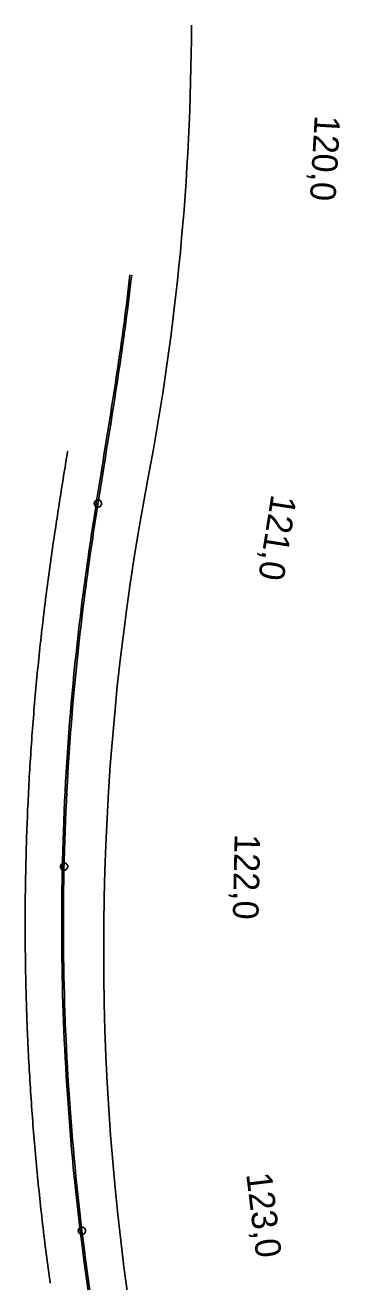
# Model space of a CAD drawing. Extents: x -670810 to -649614, y -1131928 to -1115069.
# Drawn here: x -670810 to -669949, y -1118513 to -1115069 of the extents above; entities that cross this region are included whole.
import ezdxf

# ---------------------------------------------------------------- set-up
doc = ezdxf.new("R2010")
doc.units = 0
for name, color, linetype in [('hranice_VRT_ZUR_Vysocina', 7, 'Continuous'), ('Situace - Osa koleje 2D', 7, 'Continuous'), ('Situace - Osa koleje tunel 2D', 7, 'Continuous'), ('Staničení - hlavní staničení + kolečka 1k', 7, 'Continuous')]:
    doc.layers.add(name, color=color, linetype=linetype)

# ---------------------------------------------------------------- blocks, each defined once
blk = doc.blocks.new('Sit10Kruh_98')
at = {"layer": 'Staničení - hlavní staničení + kolečka 1k'}
blk.add_lwpolyline([(10, 0), (10, 0.6), (9.9, 1.3), (9.8, 1.9), (9.7, 2.5), (9.5, 3.1), (9.3, 3.7), (9, 4.3), (8.8, 4.8), (8.4, 5.4), (8.1, 5.9), (7.7, 6.4), (7.3, 6.8), (6.8, 7.3), (6.4, 7.7), (5.9, 8.1), (5.4, 8.4), (4.8, 8.8), (4.3, 9), (3.7, 9.3), (3.1, 9.5), (2.5, 9.7), (1.9, 9.8), (1.3, 9.9), (0.6, 10), (0, 10), (-0.6, 10), (-1.3, 9.9), (-1.9, 9.8), (-2.5, 9.7), (-3.1, 9.5), (-3.7, 9.3), (-4.3, 9), (-4.8, 8.8), (-5.4, 8.4), (-5.9, 8.1), (-6.4, 7.7), (-6.8, 7.3), (-7.3, 6.8), (-7.7, 6.4), (-8.1, 5.9), (-8.4, 5.4), (-8.8, 4.8), (-9, 4.3), (-9.3, 3.7), (-9.5, 3.1), (-9.7, 2.5), (-9.8, 1.9), (-9.9, 1.3), (-10, 0.6), (-10, 0), (-10, -0.6), (-9.9, -1.3), (-9.8, -1.9), (-9.7, -2.5), (-9.5, -3.1), (-9.3, -3.7), (-9, -4.3), (-8.8, -4.8), (-8.4, -5.4), (-8.1, -5.9), (-7.7, -6.4), (-7.3, -6.8), (-6.8, -7.3), (-6.4, -7.7), (-5.9, -8.1), (-5.4, -8.4), (-4.8, -8.8), (-4.3, -9), (-3.7, -9.3), (-3.1, -9.5), (-2.5, -9.7), (-1.9, -9.8), (-1.3, -9.9), (-0.6, -10), (0, -10), (0.6, -10), (1.3, -9.9), (1.9, -9.8), (2.5, -9.7), (3.1, -9.5), (3.7, -9.3), (4.3, -9), (4.8, -8.8), (5.4, -8.4), (5.9, -8.1), (6.4, -7.7), (6.8, -7.3), (7.3, -6.8), (7.7, -6.4), (8.1, -5.9), (8.4, -5.4), (8.8, -4.8), (9, -4.3), (9.3, -3.7), (9.5, -3.1), (9.7, -2.5), (9.8, -1.9), (9.9, -1.3)], close=True, dxfattribs=at)
blk.add_circle((0, 0), 10, dxfattribs=at)
blk = doc.blocks.new('Sit10Kruh_99')
at = {"layer": 'Staničení - hlavní staničení + kolečka 1k'}
blk.add_lwpolyline([(10, 0), (9.98026, 0.6279), (9.92114, 1.25334), (9.82288, 1.87382), (9.68584, 2.4869), (9.51056, 3.09016), (9.29776, 3.68124), (9.04828, 4.2578), (8.76306, 4.81754), (8.44328, 5.35826), (8.09016, 5.87786), (7.70514, 6.37424), (7.28968, 6.84548), (6.84548, 7.28968), (6.37424, 7.70514), (5.87786, 8.09016), (5.35826, 8.44328), (4.81754, 8.76306), (4.2578, 9.04828), (3.68124, 9.29776), (3.09016, 9.51056), (2.4869, 9.68584), (1.87382, 9.82288), (1.25334, 9.92114), (0.6279, 9.98026), (0, 10), (-0.6279, 9.98026), (-1.25334, 9.92114), (-1.87382, 9.82288), (-2.4869, 9.68584), (-3.09016, 9.51056), (-3.68124, 9.29776), (-4.2578, 9.04828), (-4.81754, 8.76306), (-5.35826, 8.44328), (-5.87786, 8.09016), (-6.37424, 7.70514), (-6.84548, 7.28968), (-7.28968, 6.84548), (-7.70514, 6.37424), (-8.09016, 5.87786), (-8.44328, 5.35826), (-8.76306, 4.81754), (-9.04828, 4.2578), (-9.29776, 3.68124), (-9.51056, 3.09016), (-9.68584, 2.4869), (-9.82288, 1.87382), (-9.92114, 1.25334), (-9.98026, 0.6279), (-10, 0), (-9.98026, -0.6279), (-9.92114, -1.25334), (-9.82288, -1.87382), (-9.68584, -2.4869), (-9.51056, -3.09016), (-9.29776, -3.68124), (-9.04828, -4.2578), (-8.76306, -4.81754), (-8.44328, -5.35826), (-8.09016, -5.87786), (-7.70514, -6.37424), (-7.28968, -6.84548), (-6.84548, -7.28968), (-6.37424, -7.70514), (-5.87786, -8.09016), (-5.35826, -8.44328), (-4.81754, -8.76306), (-4.2578, -9.04828), (-3.68124, -9.29776), (-3.09016, -9.51056), (-2.4869, -9.68584), (-1.87382, -9.82288), (-1.25334, -9.92114), (-0.6279, -9.98026), (0, -10), (0.6279, -9.98026), (1.25334, -9.92114), (1.87382, -9.82288), (2.4869, -9.68584), (3.09016, -9.51056), (3.68124, -9.29776), (4.2578, -9.04828), (4.81754, -8.76306), (5.35826, -8.44328), (5.87786, -8.09016), (6.37424, -7.70514), (6.84548, -7.28968), (7.28968, -6.84548), (7.70514, -6.37424), (8.09016, -5.87786), (8.44328, -5.35826), (8.76306, -4.81754), (9.04828, -4.2578), (9.29776, -3.68124), (9.51056, -3.09016), (9.68584, -2.4869), (9.82288, -1.87382), (9.92114, -1.25334)], close=True, dxfattribs=at)
blk.add_circle((0, 0), 10, dxfattribs=at)
blk = doc.blocks.new('Sit10Kruh_100')
at = {"layer": 'Staničení - hlavní staničení + kolečka 1k'}
blk.add_lwpolyline([(10, 0), (10, 0.6), (9.9, 1.3), (9.8, 1.9), (9.7, 2.5), (9.5, 3.1), (9.3, 3.7), (9, 4.3), (8.8, 4.8), (8.4, 5.4), (8.1, 5.9), (7.7, 6.4), (7.3, 6.8), (6.8, 7.3), (6.4, 7.7), (5.9, 8.1), (5.4, 8.4), (4.8, 8.8), (4.3, 9), (3.7, 9.3), (3.1, 9.5), (2.5, 9.7), (1.9, 9.8), (1.3, 9.9), (0.6, 10), (0, 10), (-0.6, 10), (-1.3, 9.9), (-1.9, 9.8), (-2.5, 9.7), (-3.1, 9.5), (-3.7, 9.3), (-4.3, 9), (-4.8, 8.8), (-5.4, 8.4), (-5.9, 8.1), (-6.4, 7.7), (-6.8, 7.3), (-7.3, 6.8), (-7.7, 6.4), (-8.1, 5.9), (-8.4, 5.4), (-8.8, 4.8), (-9, 4.3), (-9.3, 3.7), (-9.5, 3.1), (-9.7, 2.5), (-9.8, 1.9), (-9.9, 1.3), (-10, 0.6), (-10, 0), (-10, -0.6), (-9.9, -1.3), (-9.8, -1.9), (-9.7, -2.5), (-9.5, -3.1), (-9.3, -3.7), (-9, -4.3), (-8.8, -4.8), (-8.4, -5.4), (-8.1, -5.9), (-7.7, -6.4), (-7.3, -6.8), (-6.8, -7.3), (-6.4, -7.7), (-5.9, -8.1), (-5.4, -8.4), (-4.8, -8.8), (-4.3, -9), (-3.7, -9.3), (-3.1, -9.5), (-2.5, -9.7), (-1.9, -9.8), (-1.3, -9.9), (-0.6, -10), (0, -10), (0.6, -10), (1.3, -9.9), (1.9, -9.8), (2.5, -9.7), (3.1, -9.5), (3.7, -9.3), (4.3, -9), (4.8, -8.8), (5.4, -8.4), (5.9, -8.1), (6.4, -7.7), (6.8, -7.3), (7.3, -6.8), (7.7, -6.4), (8.1, -5.9), (8.4, -5.4), (8.8, -4.8), (9, -4.3), (9.3, -3.7), (9.5, -3.1), (9.7, -2.5), (9.8, -1.9), (9.9, -1.3)], close=True, dxfattribs=at)
blk.add_circle((0, 0), 10, dxfattribs=at)

msp = doc.modelspace()

# ---------------------------------------------------------------- linework, layer by layer
at = {"layer": 'hranice_VRT_ZUR_Vysocina'}
msp.add_lwpolyline([(-670693.9, -1116236.6), (-670695.3, -1116246.1), (-670696.8, -1116255.2), (-670698.4, -1116265.1), (-670700, -1116275), (-670701.6, -1116284.9), (-670703.1, -1116294.8), (-670704.7, -1116304.7), (-670706.3, -1116314.6), (-670707.9, -1116324.5), (-670709.5, -1116334.4), (-670711, -1116344.4), (-670712.6, -1116354.3), (-670714.2, -1116364.2), (-670715.7, -1116374.2), (-670717.3, -1116384.1), (-670718.8, -1116394.1), (-670720.4, -1116404.1), (-670721.9, -1116414), (-670723.4, -1116424), (-670724.9, -1116434), (-670726.4, -1116444), (-670727.9, -1116453.9), (-670729.4, -1116463.9), (-670730.9, -1116473.9), (-670732.4, -1116483.9), (-670733.8, -1116493.9), (-670735.3, -1116503.9), (-670736.7, -1116514), (-670738.1, -1116524), (-670739.6, -1116534), (-670741, -1116544), (-670742.3, -1116554.1), (-670743.7, -1116564.1), (-670745.1, -1116574.2), (-670746.4, -1116584.2), (-670747.8, -1116594.2), (-670749.1, -1116604.3), (-670750.4, -1116614.4), (-670751.7, -1116624.4), (-670753, -1116634.5), (-670754.3, -1116644.5), (-670755.6, -1116654.6), (-670756.8, -1116664.7), (-670758, -1116674.8), (-670759.3, -1116684.8), (-670760.5, -1116694.9), (-670761.1, -1116700.5), (-670761.7, -1116705), (-670762.8, -1116715.1), (-670764, -1116725.2), (-670765.1, -1116735.2), (-670766.3, -1116745.3), (-670767.4, -1116755.4), (-670768.5, -1116765.5), (-670769.6, -1116775.6), (-670770.6, -1116785.7), (-670771.7, -1116795.8), (-670772.8, -1116805.9), (-670773.8, -1116816), (-670774.8, -1116826.1), (-670775.8, -1116836.2), (-670776.8, -1116846.3), (-670777.8, -1116856.4), (-670778.7, -1116866.5), (-670779.7, -1116876.6), (-670780.6, -1116886.7), (-670781.5, -1116896.8), (-670782.4, -1116906.9), (-670783.3, -1116917), (-670784.2, -1116927.1), (-670785, -1116937.2), (-670785.9, -1116947.4), (-670786.7, -1116957.5), (-670787.5, -1116967.6), (-670788.3, -1116977.7), (-670789.1, -1116987.8), (-670789.9, -1116998), (-670790.6, -1117008.1), (-670791.4, -1117018.2), (-670792.1, -1117028.3), (-670792.8, -1117038.4), (-670793.5, -1117048.6), (-670794.2, -1117058.7), (-670794.9, -1117068.8), (-670795.5, -1117079), (-670796.2, -1117089.1), (-670796.8, -1117099.2), (-670797.4, -1117109.3), (-670798, -1117119.5), (-670798.6, -1117129.6), (-670799.1, -1117139.7), (-670799.7, -1117149.9), (-670800.2, -1117160), (-670800.8, -1117170.1), (-670801.3, -1117180.3), (-670801.8, -1117190.4), (-670802.2, -1117200.6), (-670802.7, -1117210.7), (-670803.2, -1117220.8), (-670803.6, -1117231), (-670804, -1117241.1), (-670804.4, -1117251.3), (-670804.8, -1117261.4), (-670805.2, -1117271.5), (-670805.6, -1117281.7), (-670805.9, -1117291.8), (-670806.3, -1117302), (-670806.6, -1117312.1), (-670806.9, -1117322.3), (-670807.2, -1117332.4), (-670807.5, -1117342.6), (-670807.7, -1117352.7), (-670808, -1117362.8), (-670808.2, -1117373), (-670808.4, -1117383.1), (-670808.6, -1117393.3), (-670808.8, -1117403.4), (-670809, -1117413.6), (-670809.2, -1117423.7), (-670809.3, -1117433.9), (-670809.4, -1117444), (-670809.6, -1117454.2), (-670809.7, -1117464.3), (-670809.8, -1117474.5), (-670809.8, -1117484.6), (-670809.9, -1117494.8), (-670809.9, -1117504.9), (-670810, -1117515.1), (-670810, -1117525.2), (-670810, -1117535.4), (-670810, -1117545.5), (-670810, -1117555.7), (-670809.9, -1117565.8), (-670809.9, -1117576), (-670809.8, -1117586.1), (-670809.7, -1117596.3), (-670809.6, -1117606.4), (-670809.5, -1117616.6), (-670809.4, -1117626.7), (-670809.2, -1117636.9), (-670809.1, -1117647), (-670808.9, -1117657.2), (-670808.7, -1117667.3), (-670808.5, -1117677.5), (-670808.3, -1117687.6), (-670808.1, -1117697.8), (-670807.8, -1117707.9), (-670807.6, -1117718), (-670807.3, -1117728.2), (-670807, -1117738.3), (-670806.7, -1117748.5), (-670806.4, -1117758.6), (-670806.1, -1117768.8), (-670805.7, -1117778.9), (-670805.4, -1117789.1), (-670805, -1117799.2), (-670804.6, -1117809.3), (-670804.2, -1117819.5), (-670803.8, -1117829.6), (-670803.3, -1117839.8), (-670802.9, -1117849.9), (-670802.4, -1117860), (-670802, -1117870.2), (-670801.5, -1117880.3), (-670801, -1117890.5), (-670800.5, -1117900.6), (-670799.9, -1117910.7), (-670799.4, -1117920.9), (-670798.8, -1117931), (-670798.2, -1117941.1), (-670797.6, -1117951.3), (-670797, -1117961.4), (-670796.4, -1117971.5), (-670795.8, -1117981.7), (-670795.1, -1117991.8), (-670794.5, -1118001.9), (-670793.8, -1118012), (-670793.1, -1118022.2), (-670792.4, -1118032.3), (-670791.7, -1118042.4), (-670790.9, -1118052.5), (-670790.2, -1118062.7), (-670789.4, -1118072.8), (-670788.6, -1118082.9), (-670787.8, -1118093), (-670787, -1118103.1), (-670786.2, -1118113.3), (-670785.4, -1118123.4), (-670784.5, -1118133.5), (-670783.7, -1118143.6), (-670782.8, -1118153.7), (-670781.9, -1118163.8), (-670781, -1118173.9), (-670780.1, -1118184), (-670779.1, -1118194.1), (-670778.2, -1118204.2), (-670777.2, -1118214.3), (-670776.2, -1118224.4), (-670775.2, -1118234.5), (-670774.2, -1118244.6), (-670773.2, -1118254.7), (-670772.1, -1118264.8), (-670771.1, -1118274.9), (-670770, -1118285), (-670768.9, -1118295.1), (-670767.8, -1118305.2), (-670766.7, -1118315.3), (-670765.6, -1118325.4), (-670764.5, -1118335.5), (-670763.3, -1118345.6), (-670762.1, -1118355.6), (-670761, -1118365.7), (-670759.8, -1118375.8), (-670758.6, -1118385.9), (-670757.3, -1118395.9), (-670756.1, -1118406), (-670754.8, -1118416.1), (-670753.6, -1118426.2), (-670752.3, -1118436.2), (-670751, -1118446.3), (-670749.7, -1118456.4), (-670748.3, -1118466.4), (-670747, -1118476.5), (-670745.6, -1118486.5), (-670744.3, -1118496.6), (-670742.9, -1118506.7), (-670741.5, -1118516.7)], dxfattribs=at)
for centre, radius, start, end in [((-677058.9, -1115053.7), 6704.1, 349.21643, 359.86609), ((-663695.1, -1117599), 6900, 169.21643, 188.47877)]:
    msp.add_arc(centre, radius, start, end, dxfattribs=at)
at = {"layer": 'Situace - Osa koleje 2D'}
for points in [[(-670523.1, -1115753.8), (-670525, -1115770.3), (-670526.9, -1115786.8), (-670528.9, -1115803.3), (-670530.9, -1115819.8), (-670533, -1115836.3), (-670535.1, -1115852.8), (-670537.2, -1115869.2), (-670539.4, -1115885.7), (-670541.6, -1115902.2), (-670543.8, -1115918.6), (-670546.1, -1115935.1), (-670548.4, -1115951.5), (-670550.8, -1115968), (-670553.2, -1115984.4), (-670555.6, -1116000.9), (-670558, -1116017.3), (-670560.5, -1116033.7), (-670563, -1116050.2), (-670565.5, -1116066.6), (-670568.1, -1116083), (-670570.6, -1116099.4), (-670573.2, -1116115.9), (-670575.8, -1116132.3), (-670578.4, -1116148.7), (-670581, -1116165.1), (-670583.6, -1116181.5), (-670586.3, -1116197.9), (-670588.9, -1116214.3), (-670591.6, -1116230.7), (-670594.2, -1116247.1)], [(-670518.4, -1115754.6), (-670520.3, -1115770.8), (-670522.2, -1115787), (-670524.1, -1115803.1), (-670526.1, -1115819.3), (-670528.1, -1115835.4), (-670530.2, -1115851.5), (-670532.2, -1115867.7), (-670534.4, -1115883.8), (-670536.5, -1115899.9), (-670538.7, -1115916), (-670541, -1115932.1), (-670543.2, -1115948.2), (-670545.5, -1115964.3), (-670547.9, -1115980.4), (-670550.2, -1115996.5), (-670552.6, -1116012.6), (-670555, -1116028.7), (-670557.4, -1116044.8), (-670559.9, -1116060.8), (-670562.4, -1116076.9), (-670564.9, -1116093), (-670567.4, -1116109.1), (-670569.9, -1116125.1), (-670572.4, -1116141.2), (-670575, -1116157.3), (-670577.6, -1116173.3), (-670580.1, -1116189.4), (-670582.7, -1116205.4), (-670585.3, -1116221.5), (-670587.9, -1116237.5), (-670590.5, -1116253.6)], [(-670594.2, -1116247.1), (-670596.9, -1116263.7), (-670599.5, -1116280.2), (-670602.2, -1116296.8), (-670604.8, -1116313.4), (-670607.5, -1116329.9), (-670610.1, -1116346.5), (-670612.7, -1116363.1), (-670615.4, -1116379.6), (-670617.9, -1116396.2), (-670620.5, -1116412.8), (-670623.1, -1116429.4), (-670625.6, -1116445.9), (-670628.1, -1116462.5), (-670630.6, -1116479.1), (-670633, -1116495.7), (-670635.4, -1116512.3), (-670637.8, -1116528.9), (-670640.2, -1116545.5), (-670642.5, -1116562.1), (-670644.8, -1116578.7), (-670647.1, -1116595.4), (-670649.3, -1116612), (-670651.5, -1116628.6), (-670653.6, -1116645.3), (-670655.7, -1116661.9), (-670657.8, -1116678.6), (-670659.8, -1116695.2), (-670661.8, -1116711.9)], [(-670590.5, -1116253.6), (-670593.2, -1116270.6), (-670595.9, -1116287.5), (-670598.7, -1116304.5), (-670601.4, -1116321.5), (-670604.1, -1116338.4), (-670606.8, -1116355.4), (-670609.5, -1116372.4), (-670612.1, -1116389.4), (-670614.8, -1116406.3), (-670617.4, -1116423.3), (-670620, -1116440.3), (-670622.6, -1116457.3), (-670625.1, -1116474.3), (-670627.6, -1116491.3), (-670630.1, -1116508.3), (-670632.6, -1116525.3), (-670635, -1116542.3), (-670637.4, -1116559.4), (-670639.7, -1116576.4), (-670642, -1116593.4), (-670644.3, -1116610.4), (-670646.6, -1116627.5), (-670648.8, -1116644.5), (-670650.9, -1116661.6), (-670653, -1116678.6), (-670655.1, -1116695.7), (-670657.1, -1116712.7)]]:
    msp.add_lwpolyline(points, dxfattribs=at)
for radius, start, end in [(7004.7, 173.2726, 180.35111), (7000, 173.27534, 180.35111), (7004.7, 186.8992, 197.32601), (7000, 186.8992, 197.29879)]:
    msp.add_arc((-663705.3, -1117532.4), radius, start, end, dxfattribs=at)
at = {"layer": 'Situace - Osa koleje tunel 2D'}
for radius in [7004.7, 7000]:
    msp.add_arc((-663705.3, -1117532.4), radius, 180.35111, 186.8992, dxfattribs=at)

# ---------------------------------------------------------------- block references
at = {"layer": 'Staničení - hlavní staničení + kolečka 1k'}
for name, p, rotation in [('Sit10Kruh_98', (-670610.7, -1116380.5), -98.909321), ('Sit10Kruh_99', (-670703.5, -1117375.3), -91.28591100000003), ('Sit10Kruh_100', (-670654.6, -1118373.3), -83.10079999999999)]:
    msp.add_blockref(name, p, dxfattribs=dict(at, rotation=rotation))

# ---------------------------------------------------------------- texts
for s, rotation, p in [('120,0', 266.6993, (-670017.1, -1115315.4)), ('121,0', 261.0907, (-670135.8, -1116353.4)), ('122,0', 268.7141, (-670236.4, -1117285.6)), ('123,0', 276.8992, (-670205, -1118217.9))]:
    msp.add_text(s, height=70, rotation=rotation, dxfattribs=at).set_placement(p)

doc.saveas('drawing.dxf')
